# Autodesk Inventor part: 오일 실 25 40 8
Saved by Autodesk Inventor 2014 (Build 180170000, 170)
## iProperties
Created: 2026-04
Part Number: 오일 실 25 40 8
Material: 일반
Document SubType Name: Modeling
Designer: dg
Density: 1 g/cm^3
Appearance: 기본값
Author: dg
Author: jhkim
Description: 오일-실
Creation Date: 2026-03-27
Sending System: Autodesk Inventor 2026
Preprocessor: ST-DEVELOPER v20.1
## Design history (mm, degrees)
node "오일 실 25 40 81"
body "Solid1"
node "기준1"
